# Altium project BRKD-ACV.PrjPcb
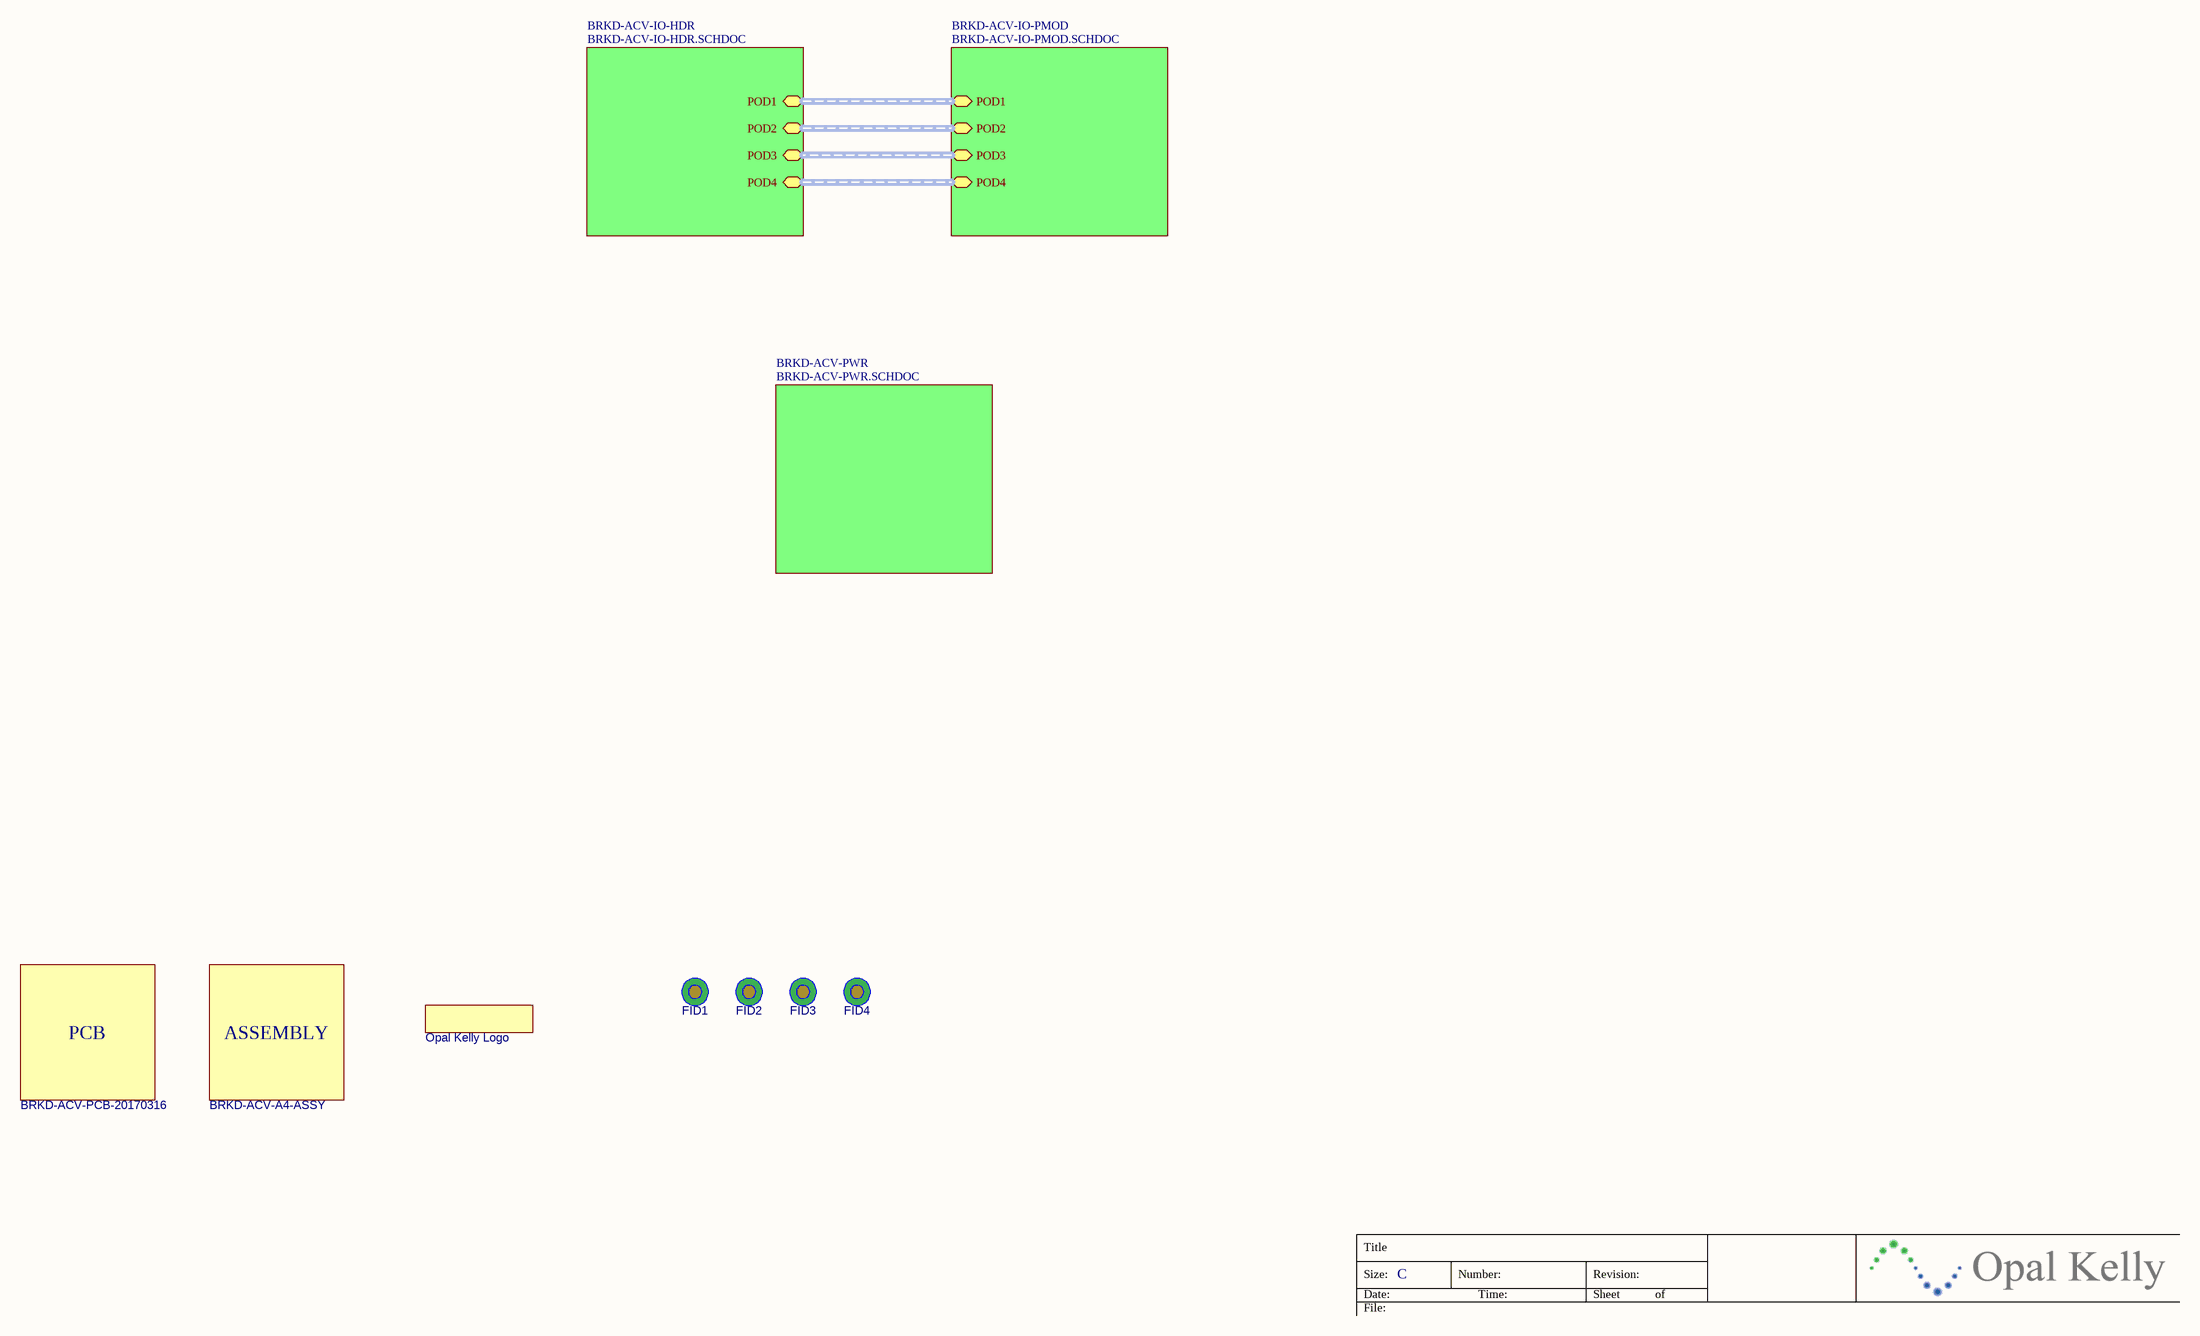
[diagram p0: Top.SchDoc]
Assembly_Part_Num: BRKD-ACV; Assembly_Revision: C01; PCB_Part_Num: BRKD-ACV-PCB; PCB_Revision: 20170316
4 sheets, 173 parts. Net scope: hierarchical (ports join the sheet entries above them; power ports are global).
Board file: BRKD-ACV.PcbDoc
Sheets:
  Top.SchDoc
    BRKD-ACV-IO-HDR = BRKD-ACV-IO-HDR.SCHDOC
    BRKD-ACV-IO-PMOD = BRKD-ACV-IO-PMOD.SCHDOC
    BRKD-ACV-PWR = BRKD-ACV-PWR.SCHDOC

## Sheet Top.SchDoc: FOMD-ACV Breakout Board - Top
size C; Organization: Opal Kelly; Address1: 13500 SW 72nd Ave; Address2: Suite 120; Address3: Portland, OR  97223; Address4: http://www.opalkelly.com; DocumentNumber: xxx; Revision: 1; SheetNumber: 1; SheetTotal: 4; PageSetup: Record=PageOptions¦CenterHorizontal=True¦CenterVertical=True¦PrintScale=0.52¦XCorrection=1.00¦YCorrection=1.00¦PrintKind=0¦BorderSize=5000000¦LeftOffset=0¦BottomOffset=0¦Orientation=2¦PaperLength=1000¦PaperWidth=1000¦Scale=100¦PaperSource=15¦PrintQuality=600¦MediaType=1¦DitherType=10¦PaperKind=Letter¦PrintScaleMode=1

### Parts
*1  Opal Kelly Logo  [okLogo-23x5]
ASSY1  BRKD-ACV-A4-ASSY  (mechanical)
FID1  FIDUCIAL  [FID1MM/2MM-SS]  (value not drawn)
FID2  FIDUCIAL  [FID1MM/2MM-SS]  (value not drawn)
FID3  FIDUCIAL  [FID1MM/2MM-SS]  (value not drawn)
FID4  FIDUCIAL  [FID1MM/2MM-SS]  (value not drawn)
PCB?  BRKD-ACV-PCB-20170316  (mechanical)

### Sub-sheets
BRKD-ACV-IO-HDR = BRKD-ACV-IO-HDR.SCHDOC: POD1 (harness POD), POD2 (harness POD), POD3 (harness POD), POD4 (harness POD)
BRKD-ACV-IO-PMOD = BRKD-ACV-IO-PMOD.SCHDOC: POD1 (harness POD), POD2 (harness POD), POD3 (harness POD), POD4 (harness POD)
BRKD-ACV-PWR = BRKD-ACV-PWR.SCHDOC: no entries

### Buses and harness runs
harness sheet BRKD-ACV-IO-HDR/POD1 = sheet BRKD-ACV-IO-PMOD/POD1
harness sheet BRKD-ACV-IO-HDR/POD2 = sheet BRKD-ACV-IO-PMOD/POD2
harness sheet BRKD-ACV-IO-HDR/POD3 = sheet BRKD-ACV-IO-PMOD/POD3
harness sheet BRKD-ACV-IO-HDR/POD4 = sheet BRKD-ACV-IO-PMOD/POD4

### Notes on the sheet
- Title
- Size:
- Date:
- File:
- C
- Number:
- Time:
- Revision:
- Sheet
- of

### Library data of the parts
*1 = OKLOGO
ASSY1 = 001379: BRKD-ACV-A4 PCB assembly; Manufacturer: PCB Assembly Cost; partnumber: 001379
FID1-FID4 = FIDUCIAL: PCB fiducial
PCB? = 001516: PCB for BRKD-ACV; Manufacturer: Generic PCB Manufacturer; partnumber: 001516; x_lifecycle_status: Prototype

## Sheet BRKD-ACV-IO-HDR.SCHDOC: FOMD-ACV Breakout Board - Headers
size C; Organization: Opal Kelly; Address1: 13500 SW 72nd Ave; Address2: STE 100; Address3: (217)391-3724; Address4: http://www.opalkelly.com; DocumentNumber: 1; Revision: 1.0; SheetNumber: 1; SheetTotal: 3
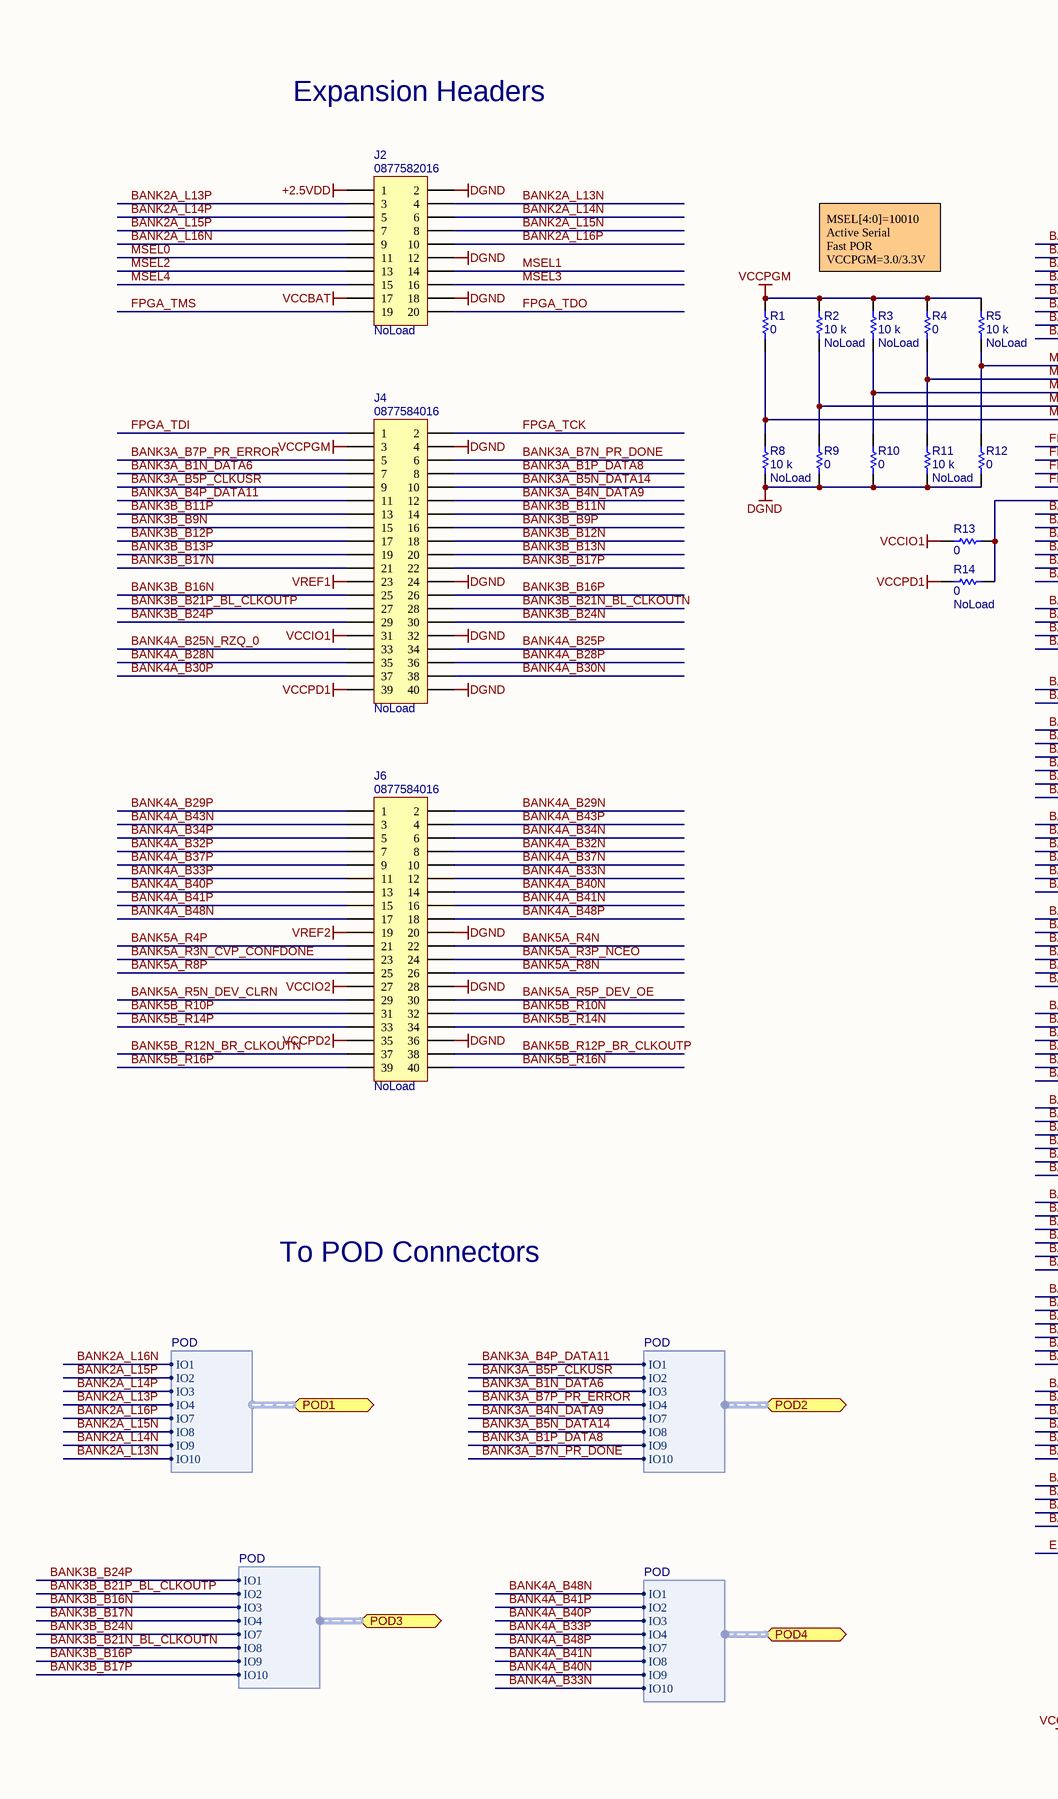
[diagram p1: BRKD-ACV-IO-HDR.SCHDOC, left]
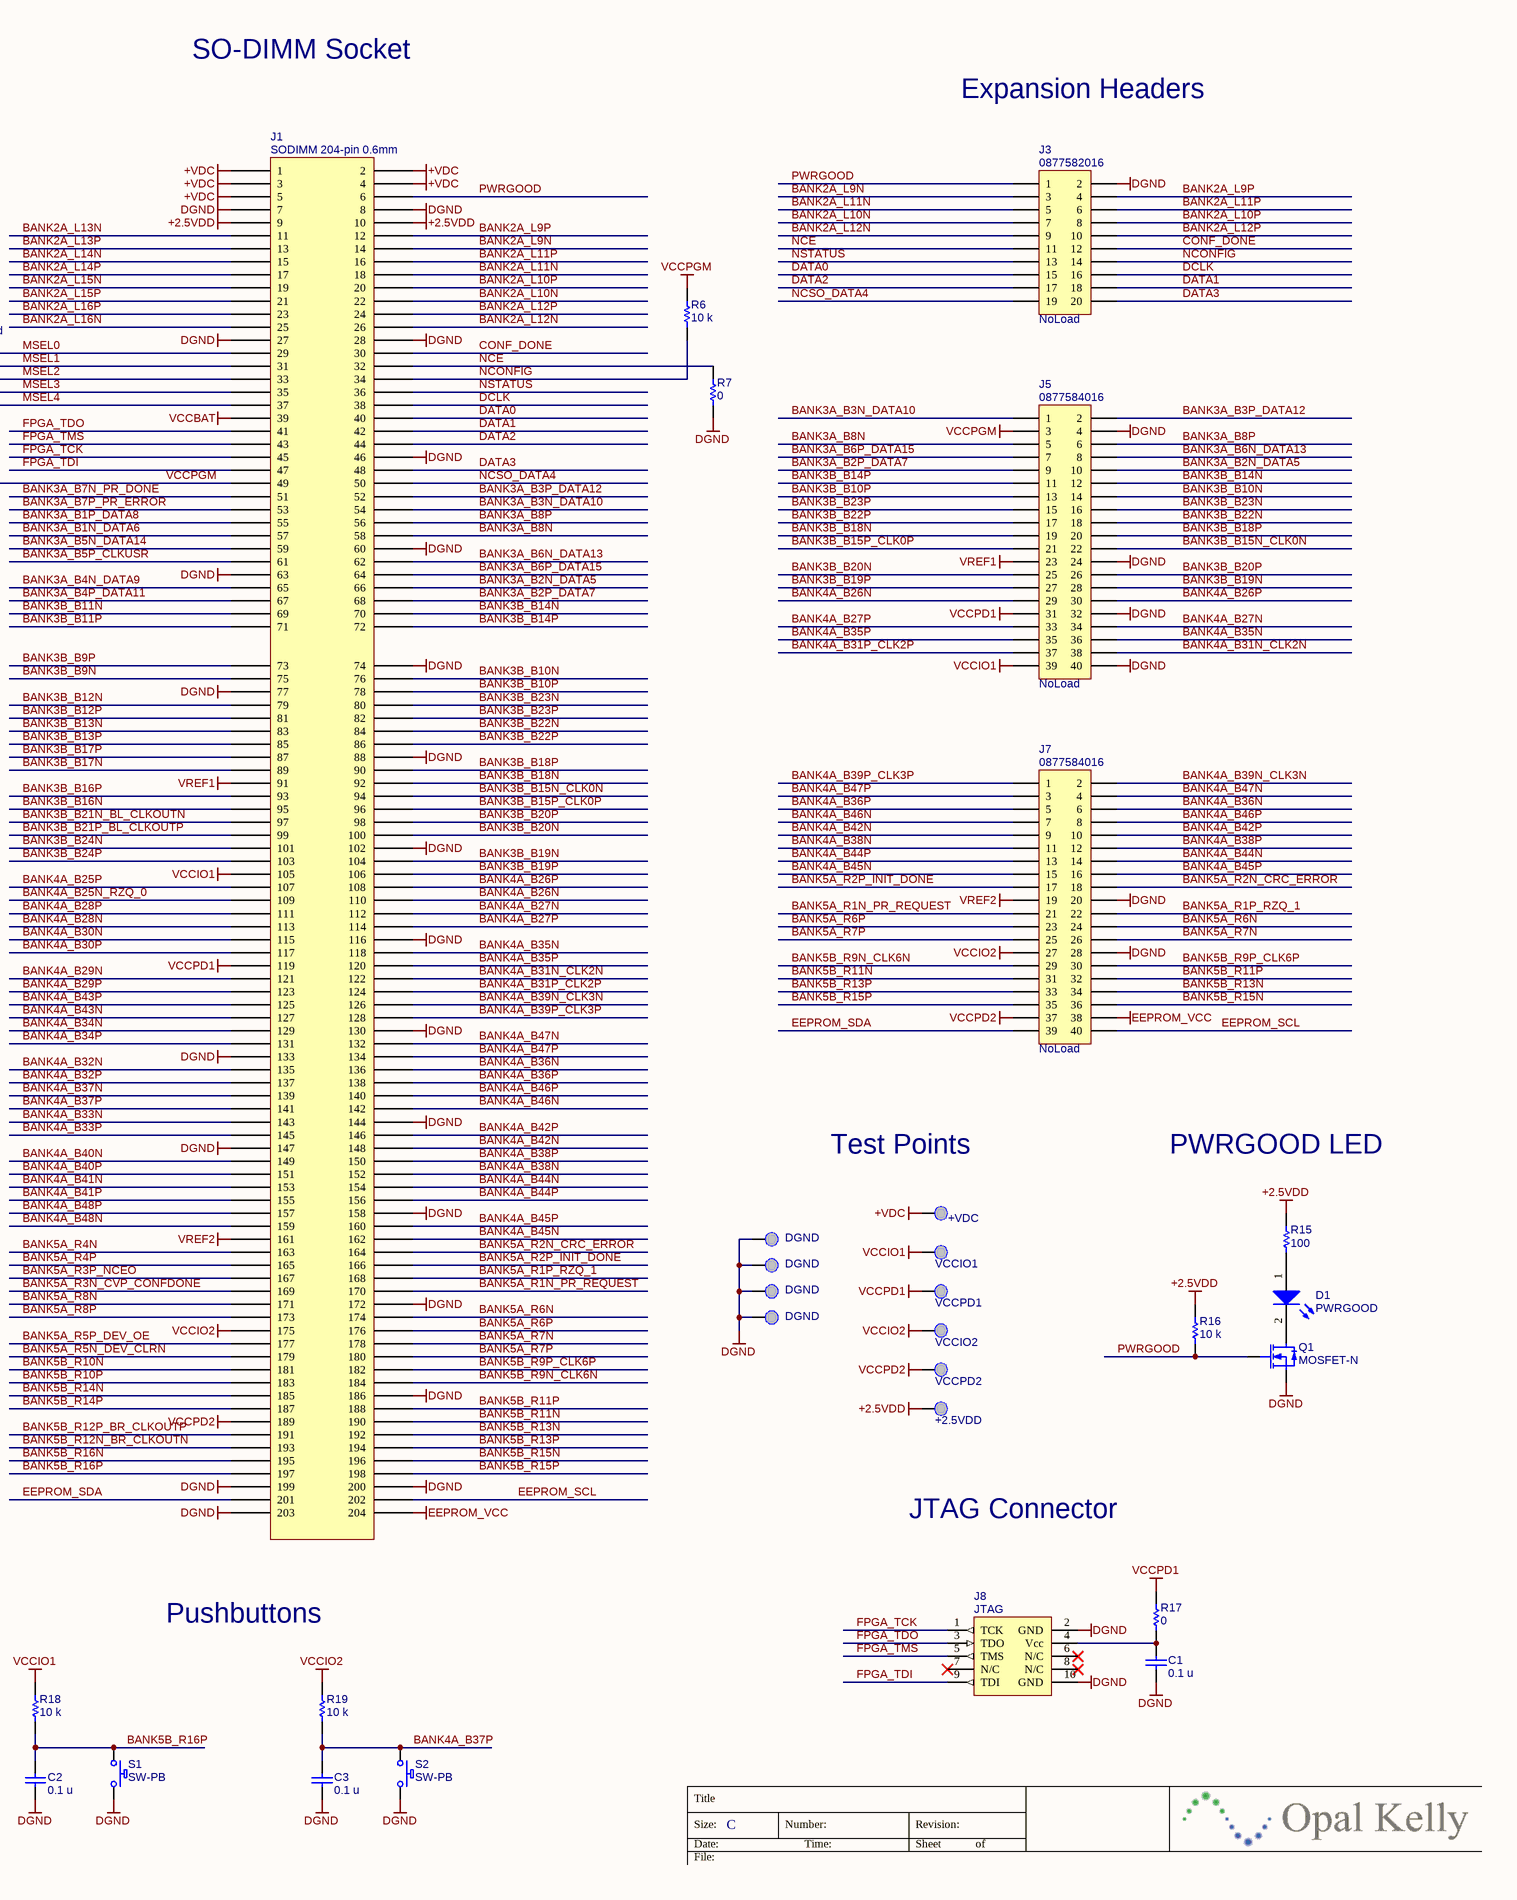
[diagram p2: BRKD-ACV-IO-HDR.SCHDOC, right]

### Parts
C1  value 0.1 u  [CAPC1005X06N]  (hidden comment: C0402C104K8PACTU)
C2  value 0.1 u  [CAPC1005X06N]  (hidden comment: C0402C104K8PACTU)
C3  value 0.1 u  [CAPC1005X06N]  (hidden comment: C0402C104K8PACTU)
D1  PWRGOOD  [CD1608-0603]
J1  SODIMM 204-pin 0.6mm  [2013289]
J2  0877582016  [HDR2X10-2MM]
J3  0877582016  [HDR2X10-2MM]
J4  0877584016  [HDR2X20-2MM]
J5  0877584016  [HDR2X20-2MM]
J6  0877584016  [HDR2X20-2MM]
J7  0877584016  [HDR2X20-2MM]
J8  JTAG  [HDR2X5-SHRD]
Q1  MOSFET-N  [SOT23-95P240X110]
R1  value 0  [RESC1005X06N]  (hidden comment: CRCW04020000Z0ED)
R2  value 10 k  [RESC1005X06N]  (hidden comment: CRCW040210K0JNED)
R3  value 10 k  [RESC1005X06N]  (hidden comment: CRCW040210K0JNED)
R4  value 0  [RESC1005X06N]  (hidden comment: CRCW04020000Z0ED)
R5  value 10 k  [RESC1005X06N]  (hidden comment: CRCW040210K0JNED)
R6  value 10 k  [RESC1005X06N]  (hidden comment: CRCW040210K0JNED)
R7  value 0  [RESC1005X06N]  (hidden comment: CRCW04020000Z0ED)
R8  value 10 k  [RESC1005X06N]  (hidden comment: CRCW040210K0JNED)
R9  value 0  [RESC1005X06N]  (hidden comment: CRCW04020000Z0ED)
R10  value 0  [RESC1005X06N]  (hidden comment: CRCW04020000Z0ED)
R11  value 10 k  [RESC1005X06N]  (hidden comment: CRCW040210K0JNED)
R12  value 0  [RESC1005X06N]  (hidden comment: CRCW04020000Z0ED)
R13  value 0  [RESC1608N]  (hidden comment: CRCW06030000Z0EA)
R14  value 0  [RESC1608N]  (hidden comment: CRCW06030000Z0EA)
R15  value 100  [RESC1005X06N]  (hidden comment: CRCW0402100RFKED)
R16  value 10 k  [RESC1005X06N]  (hidden comment: CRCW040210K0JNED)
R17  value 0  [RESC1608N]  (hidden comment: CRCW06030000Z0EA)
R18  value 10 k  [RESC1005X06N]  (hidden comment: CRCW040210K0JNED)
R19  value 10 k  [RESC1005X06N]  (hidden comment: CRCW040210K0JNED)
S1  SW-PB  [SW_BFS]
S2  SW-PB  [SW_BFS]
TP1  +VDC  [TP_MED]
TP2  DGND  [TP_MED]
TP3  VCCIO1  [TP_MED]
TP4  DGND  [TP_MED]
TP5  DGND  [TP_MED]
TP6  VCCPD1  [TP_MED]
TP7  DGND  [TP_MED]
TP8  VCCIO2  [TP_MED]
TP9  VCCPD2  [TP_MED]
TP10  +2.5VDD  [TP_MED]

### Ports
POD1 (harness POD), POD2 (harness POD), POD3 (harness POD), POD4 (harness POD)

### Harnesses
POD: IO1, IO2, IO3, IO4, IO7, IO8, IO9, IO10

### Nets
+2.5VDD: J1.9 J1.10 J2.1 R15.2 R16.2 TP10.1(PIN)
+VDC: J1.1 J1.2 J1.3 J1.4 J1.5 TP1.1(PIN)
DGND: C1.1 C2.1 C3.1 J1.7 J1.8 J1.27 J1.28 J1.46 J1.60 J1.63 J1.74 J1.77 J1.88 J1.102 J1.116 J1.130 J1.133 J1.144 J1.147 J1.158 J1.172 J1.186 J1.199 J1.200 J1.203 J2.2 J2.12 J2.18 J3.2 J4.4 J4.24 J4.32 J4.40 J5.4 J5.24 J5.32 J5.40 J6.20 J6.28 J6.36 J7.20 J7.28 J8.2(GND) J8.10(GND) Q1.2(S) R7.1 R8.2 R9.1 R10.1 R11.2 R12.1 S1.2 S2.2 TP2.1(PIN) TP4.1(PIN) TP5.1(PIN) TP7.1(PIN)
EEPROM_VCC: J1.204 J7.38
VCCBAT: J1.39 J2.17
VCCIO1: J1.105 J4.31 J5.39 R13.1 R18.2 TP3.1(PIN)
VCCIO2: J1.175 J6.27 J7.27 R19.2 TP8.1(PIN)
VCCPD1: J1.119 J4.39 J5.31 R14.1 R17.2 TP6.1(PIN)
VCCPD2: J1.189 J6.35 J7.37 TP9.1(PIN)
VCCPGM: J1.49 J4.3 J5.3 R1.2 R2.2 R3.1 R4.2 R5.1 R6.2 R13.2 R14.2
VREF1: J1.91 J4.23 J5.23
VREF2: J1.161 J6.19 J7.19
BANK2A_L9N: J1.14 J3.3
BANK2A_L9P: J1.12 J3.4
BANK2A_L10N: J1.22 J3.7
BANK2A_L10P: J1.20 J3.8
BANK2A_L11N: J1.18 J3.5
BANK2A_L11P: J1.16 J3.6
BANK2A_L12N: J1.26 J3.9
BANK2A_L12P: J1.24 J3.10
BANK2A_L13N: J1.11 J2.4 ; port POD1.IO10
BANK2A_L13P: J1.13 J2.3 ; port POD1.IO4
BANK2A_L14N: J1.15 J2.6 ; port POD1.IO9
BANK2A_L14P: J1.17 J2.5 ; port POD1.IO3
BANK2A_L15N: J1.19 J2.8 ; port POD1.IO8
BANK2A_L15P: J1.21 J2.7 ; port POD1.IO2
BANK2A_L16N: J1.25 J2.9 ; port POD1.IO1
BANK2A_L16P: J1.23 J2.10 ; port POD1.IO7
BANK3A_B1N_DATA6: J1.57 J4.7 ; port POD2.IO3
BANK3A_B1P_DATA8: J1.55 J4.8 ; port POD2.IO9
BANK3A_B2N_DATA5: J1.66 J5.10
BANK3A_B2P_DATA7: J1.68 J5.9
BANK3A_B3N_DATA10: J1.54 J5.1
BANK3A_B3P_DATA12: J1.52 J5.2
BANK3A_B4N_DATA9: J1.65 J4.12 ; port POD2.IO7
BANK3A_B4P_DATA11: J1.67 J4.11 ; port POD2.IO1
BANK3A_B5N_DATA14: J1.59 J4.10 ; port POD2.IO8
BANK3A_B5P_CLKUSR: J1.61 J4.9 ; port POD2.IO2
BANK3A_B6N_DATA13: J1.62 J5.8
BANK3A_B6P_DATA15: J1.64 J5.7
BANK3A_B7N_PR_DONE: J1.51 J4.6 ; port POD2.IO10
BANK3A_B7P_PR_ERROR: J1.53 J4.5 ; port POD2.IO4
BANK3A_B8N: J1.58 J5.5
BANK3A_B8P: J1.56 J5.6
BANK3B_B9N: J1.75 J4.15
BANK3B_B9P: J1.73 J4.16
BANK3B_B10N: J1.76 J5.14
BANK3B_B10P: J1.78 J5.13
BANK3B_B11N: J1.69 J4.14
BANK3B_B11P: J1.71 J4.13
BANK3B_B12N: J1.79 J4.18
BANK3B_B12P: J1.81 J4.17
BANK3B_B13N: J1.83 J4.20
BANK3B_B13P: J1.85 J4.19
BANK3B_B14N: J1.70 J5.12
BANK3B_B14P: J1.72 J5.11
BANK3B_B15N_CLK0N: J1.94 J5.22
BANK3B_B15P_CLK0P: J1.96 J5.21
BANK3B_B16N: J1.95 J4.25 ; port POD3.IO3
BANK3B_B16P: J1.93 J4.26 ; port POD3.IO9
BANK3B_B17N: J1.89 J4.21 ; port POD3.IO4
BANK3B_B17P: J1.87 J4.22 ; port POD3.IO10
BANK3B_B18N: J1.92 J5.19
BANK3B_B18P: J1.90 J5.20
BANK3B_B19N: J1.104 J5.28
BANK3B_B19P: J1.106 J5.27
BANK3B_B20N: J1.100 J5.25
BANK3B_B20P: J1.98 J5.26
BANK3B_B21N_BL_CLKOUTN: J1.97 J4.28 ; port POD3.IO8
BANK3B_B21P_BL_CLKOUTP: J1.99 J4.27 ; port POD3.IO2
BANK3B_B22N: J1.84 J5.18
BANK3B_B22P: J1.86 J5.17
BANK3B_B23N: J1.80 J5.16
BANK3B_B23P: J1.82 J5.15
BANK3B_B24N: J1.101 J4.30 ; port POD3.IO7
BANK3B_B24P: J1.103 J4.29 ; port POD3.IO1
BANK4A_B25N_RZQ_0: J1.109 J4.33
BANK4A_B25P: J1.107 J4.34
BANK4A_B26N: J1.110 J5.29
BANK4A_B26P: J1.108 J5.30
BANK4A_B27N: J1.112 J5.34
BANK4A_B27P: J1.114 J5.33
BANK4A_B28N: J1.113 J4.35
BANK4A_B28P: J1.111 J4.36
BANK4A_B29N: J1.121 J6.2
BANK4A_B29P: J1.123 J6.1
BANK4A_B30N: J1.115 J4.38
BANK4A_B30P: J1.117 J4.37
BANK4A_B31N_CLK2N: J1.122 J5.38
BANK4A_B31P_CLK2P: J1.124 J5.37
BANK4A_B32N: J1.135 J6.8
BANK4A_B32P: J1.137 J6.7
BANK4A_B33N: J1.143 J6.12 ; port POD4.IO10
BANK4A_B33P: J1.145 J6.11 ; port POD4.IO4
BANK4A_B34N: J1.129 J6.6
BANK4A_B34P: J1.131 J6.5
BANK4A_B35N: J1.118 J5.36
BANK4A_B35P: J1.120 J5.35
BANK4A_B36N: J1.136 J7.6
BANK4A_B36P: J1.138 J7.5
BANK4A_B37N: J1.139 J6.10
BANK4A_B37P: C3.2 J1.141 J6.9 R19.1 S2.1
BANK4A_B38N: J1.152 J7.11
BANK4A_B38P: J1.150 J7.12
BANK4A_B39N_CLK3N: J1.126 J7.2
BANK4A_B39P_CLK3P: J1.128 J7.1
BANK4A_B40N: J1.149 J6.14 ; port POD4.IO9
BANK4A_B40P: J1.151 J6.13 ; port POD4.IO3
BANK4A_B41N: J1.153 J6.16 ; port POD4.IO8
BANK4A_B41P: J1.155 J6.15 ; port POD4.IO2
BANK4A_B42N: J1.148 J7.9
BANK4A_B42P: J1.146 J7.10
BANK4A_B43N: J1.127 J6.3
BANK4A_B43P: J1.125 J6.4
BANK4A_B44N: J1.154 J7.14
BANK4A_B44P: J1.156 J7.13
BANK4A_B45N: J1.162 J7.15
BANK4A_B45P: J1.160 J7.16
BANK4A_B46N: J1.142 J7.7
BANK4A_B46P: J1.140 J7.8
BANK4A_B47N: J1.132 J7.4
BANK4A_B47P: J1.134 J7.3
BANK4A_B48N: J1.159 J6.17 ; port POD4.IO1
BANK4A_B48P: J1.157 J6.18 ; port POD4.IO7
BANK5A_R1N_PR_REQUEST: J1.170 J7.21
BANK5A_R1P_RZQ_1: J1.168 J7.22
BANK5A_R2N_CRC_ERROR: J1.164 J7.18
BANK5A_R2P_INIT_DONE: J1.166 J7.17
BANK5A_R3N_CVP_CONFDONE: J1.169 J6.23
BANK5A_R3P_NCEO: J1.167 J6.24
BANK5A_R4N: J1.163 J6.22
BANK5A_R4P: J1.165 J6.21
BANK5A_R5N_DEV_CLRN: J1.179 J6.29
BANK5A_R5P_DEV_OE: J1.177 J6.30
BANK5A_R6N: J1.174 J7.24
BANK5A_R6P: J1.176 J7.23
BANK5A_R7N: J1.178 J7.26
BANK5A_R7P: J1.180 J7.25
BANK5A_R8N: J1.171 J6.26
BANK5A_R8P: J1.173 J6.25
BANK5B_R9N_CLK6N: J1.184 J7.29
BANK5B_R9P_CLK6P: J1.182 J7.30
BANK5B_R10N: J1.181 J6.32
BANK5B_R10P: J1.183 J6.31
BANK5B_R11N: J1.190 J7.31
BANK5B_R11P: J1.188 J7.32
BANK5B_R12N_BR_CLKOUTN: J1.193 J6.37
BANK5B_R12P_BR_CLKOUTP: J1.191 J6.38
BANK5B_R13N: J1.192 J7.34
BANK5B_R13P: J1.194 J7.33
BANK5B_R14N: J1.185 J6.34
BANK5B_R14P: J1.187 J6.33
BANK5B_R15N: J1.196 J7.36
BANK5B_R15P: J1.198 J7.35
BANK5B_R16N: J1.195 J6.40
BANK5B_R16P: C2.2 J1.197 J6.39 R18.1 S1.1
CONF_DONE: J1.30 J3.12
DATA0: J1.40 J3.15
DATA1: J1.42 J3.18
DATA2: J1.44 J3.17
DATA3: J1.48 J3.20
DCLK: J1.38 J3.16
EEPROM_SCL: J1.202 J7.40
EEPROM_SDA: J1.201 J7.39
FPGA_TCK: J1.45 J4.2 J8.1(TCK)
FPGA_TDI: J1.47 J4.1 J8.9(TDI)
FPGA_TDO: J1.41 J2.20 J8.3(TDO)
FPGA_TMS: J1.43 J2.19 J8.5(TMS)
MSEL0: J1.29 J2.11 R5.2 R12.2
MSEL1: J1.31 J2.14 R4.1 R11.1
MSEL2: J1.33 J2.13 R3.2 R10.2
MSEL3: J1.35 J2.16 R2.1 R9.2
MSEL4: J1.37 J2.15 R1.1 R8.1
NCE: J1.32 J3.11 R7.2
NCONFIG: J1.34 J3.14 R6.1
NCSO_DATA4: J1.50 J3.19
NSTATUS: J1.36 J3.13
PWRGOOD: J1.6 J3.1 Q1.1(G) R16.1
NetC1_2: C1.2 J8.4(Vcc) R17.1
NetD1_1: D1.1(A) R15.1
NetD1_2: D1.2(K) Q1.3(D)

Not connected (* = marked no-connect by the designer): J8 6(N/C)* 7(N/C)* 8(N/C)*

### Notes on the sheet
- Expansion Headers
- SO-DIMM Socket
- MSEL[4:0]=10010
  Active Serial
  Fast POR
  VCCPGM=3.0/3.3V
- Test Points
- PWRGOOD LED
- To POD Connectors
- JTAG Connector
- Pushbuttons
- Title
- Size:
- Date:
- File:
- C
- Number:
- Time:
- Revision:
- Sheet
- of

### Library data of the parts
C1-C3 = 000070: Ceramic capacitor; Manufacturer: Kemet; partnumber: 000070; Description 2: SM-0402, 10%, 10v; ValueFloat: 1E-7; Tolerance (%): 10
D1 = 000012: LED; Manufacturer: Lite-On; Manufacturer_PN: LTST-C190GKT; partnumber: 000012; Description 2: SM-0603, green
J1 = 001370: SODIMM socket, DDR3, 204-pin, gold flash, 5.2mm height, surface-mount; Manufacturer: AMP / Tyco; Manufacturer_PN: 2-2013289-1; partnumber: 001370
J2 J3 = 001338: 2mm header, 10x2, thru-hole; Manufacturer: Molex; partnumber: 001338; Description 2: 15µin gold finish, vertical mount; x_lifecycle_status: Production
J4-J7 = 000583: 2mm header, 20x2, thru-hole; Manufacturer: Molex; partnumber: 000583
J8 = 000777: 2.54mm, 10 Pos, Dual Row Header; Manufacturer: Molex; Manufacturer_PN: 70246-1004; partnumber: 000777; Description 2: Altera JTAG Compatible
Q1 = 001237: N-Channel, Logic Level, MOSFET; PartNumber: 001237; Manufacturer: Fairchild Semiconductor; Manufacturer_PN: FDN337N; PackageDocument: 1995/1996; Description 2: 2.2A, 30V
R1 R4 R7 R9 R10 R12 = 000755: Thick-film resistor; Manufacturer: Vishay; partnumber: 000755; Description 2: SM-0402, 1%, 1/16W; Tolerance (%): 1
R2 R3 R5 R6 R8 R11 R16 R18 R19 = 000759: Thick-film resistor; Manufacturer: Vishay; partnumber: 000759; Description 2: SM-0402, 5%, 1/16W; ValueFloat: 10000; Tolerance (%): 5
R13 R14 R17 = 000411: Zero-ohm resistor; Manufacturer: Vishay; partnumber: 000411; Description 2: SM-0603, 1/10W, 20 mOhm max
R15 = 000827: Thick-film resistor; Manufacturer: Vishay; partnumber: 000827; Description 2: SM-0402, 1%, 1/16W; Tolerance (%): 1
S1 S2 = 000010: Pushbutton; Manufacturer: Omron; PartNumber: 000010; Manufacturer_PN: B3FS-1000P; Description 2: SMD, tactile; x_lifecycle_status: Production
TP1-TP10 = 000265: Testpoint; Manufacturer: Keystone Electronics; Manufacturer_PN: 5007; partnumber: 000265; Description 2: 0.063 in. diameter, compact, White

## Sheet BRKD-ACV-IO-PMOD.SCHDOC: FOMD-ACV Breakout Board - PMOD
size C; Organization: Opal Kelly; Address1: 13500 SW 72nd Ave; Address2: STE 100; Address3: (217)391-3724; Address4: http://www.opalkelly.com; DocumentNumber: 1; Revision: 1.0; SheetNumber: 2; SheetTotal: 3
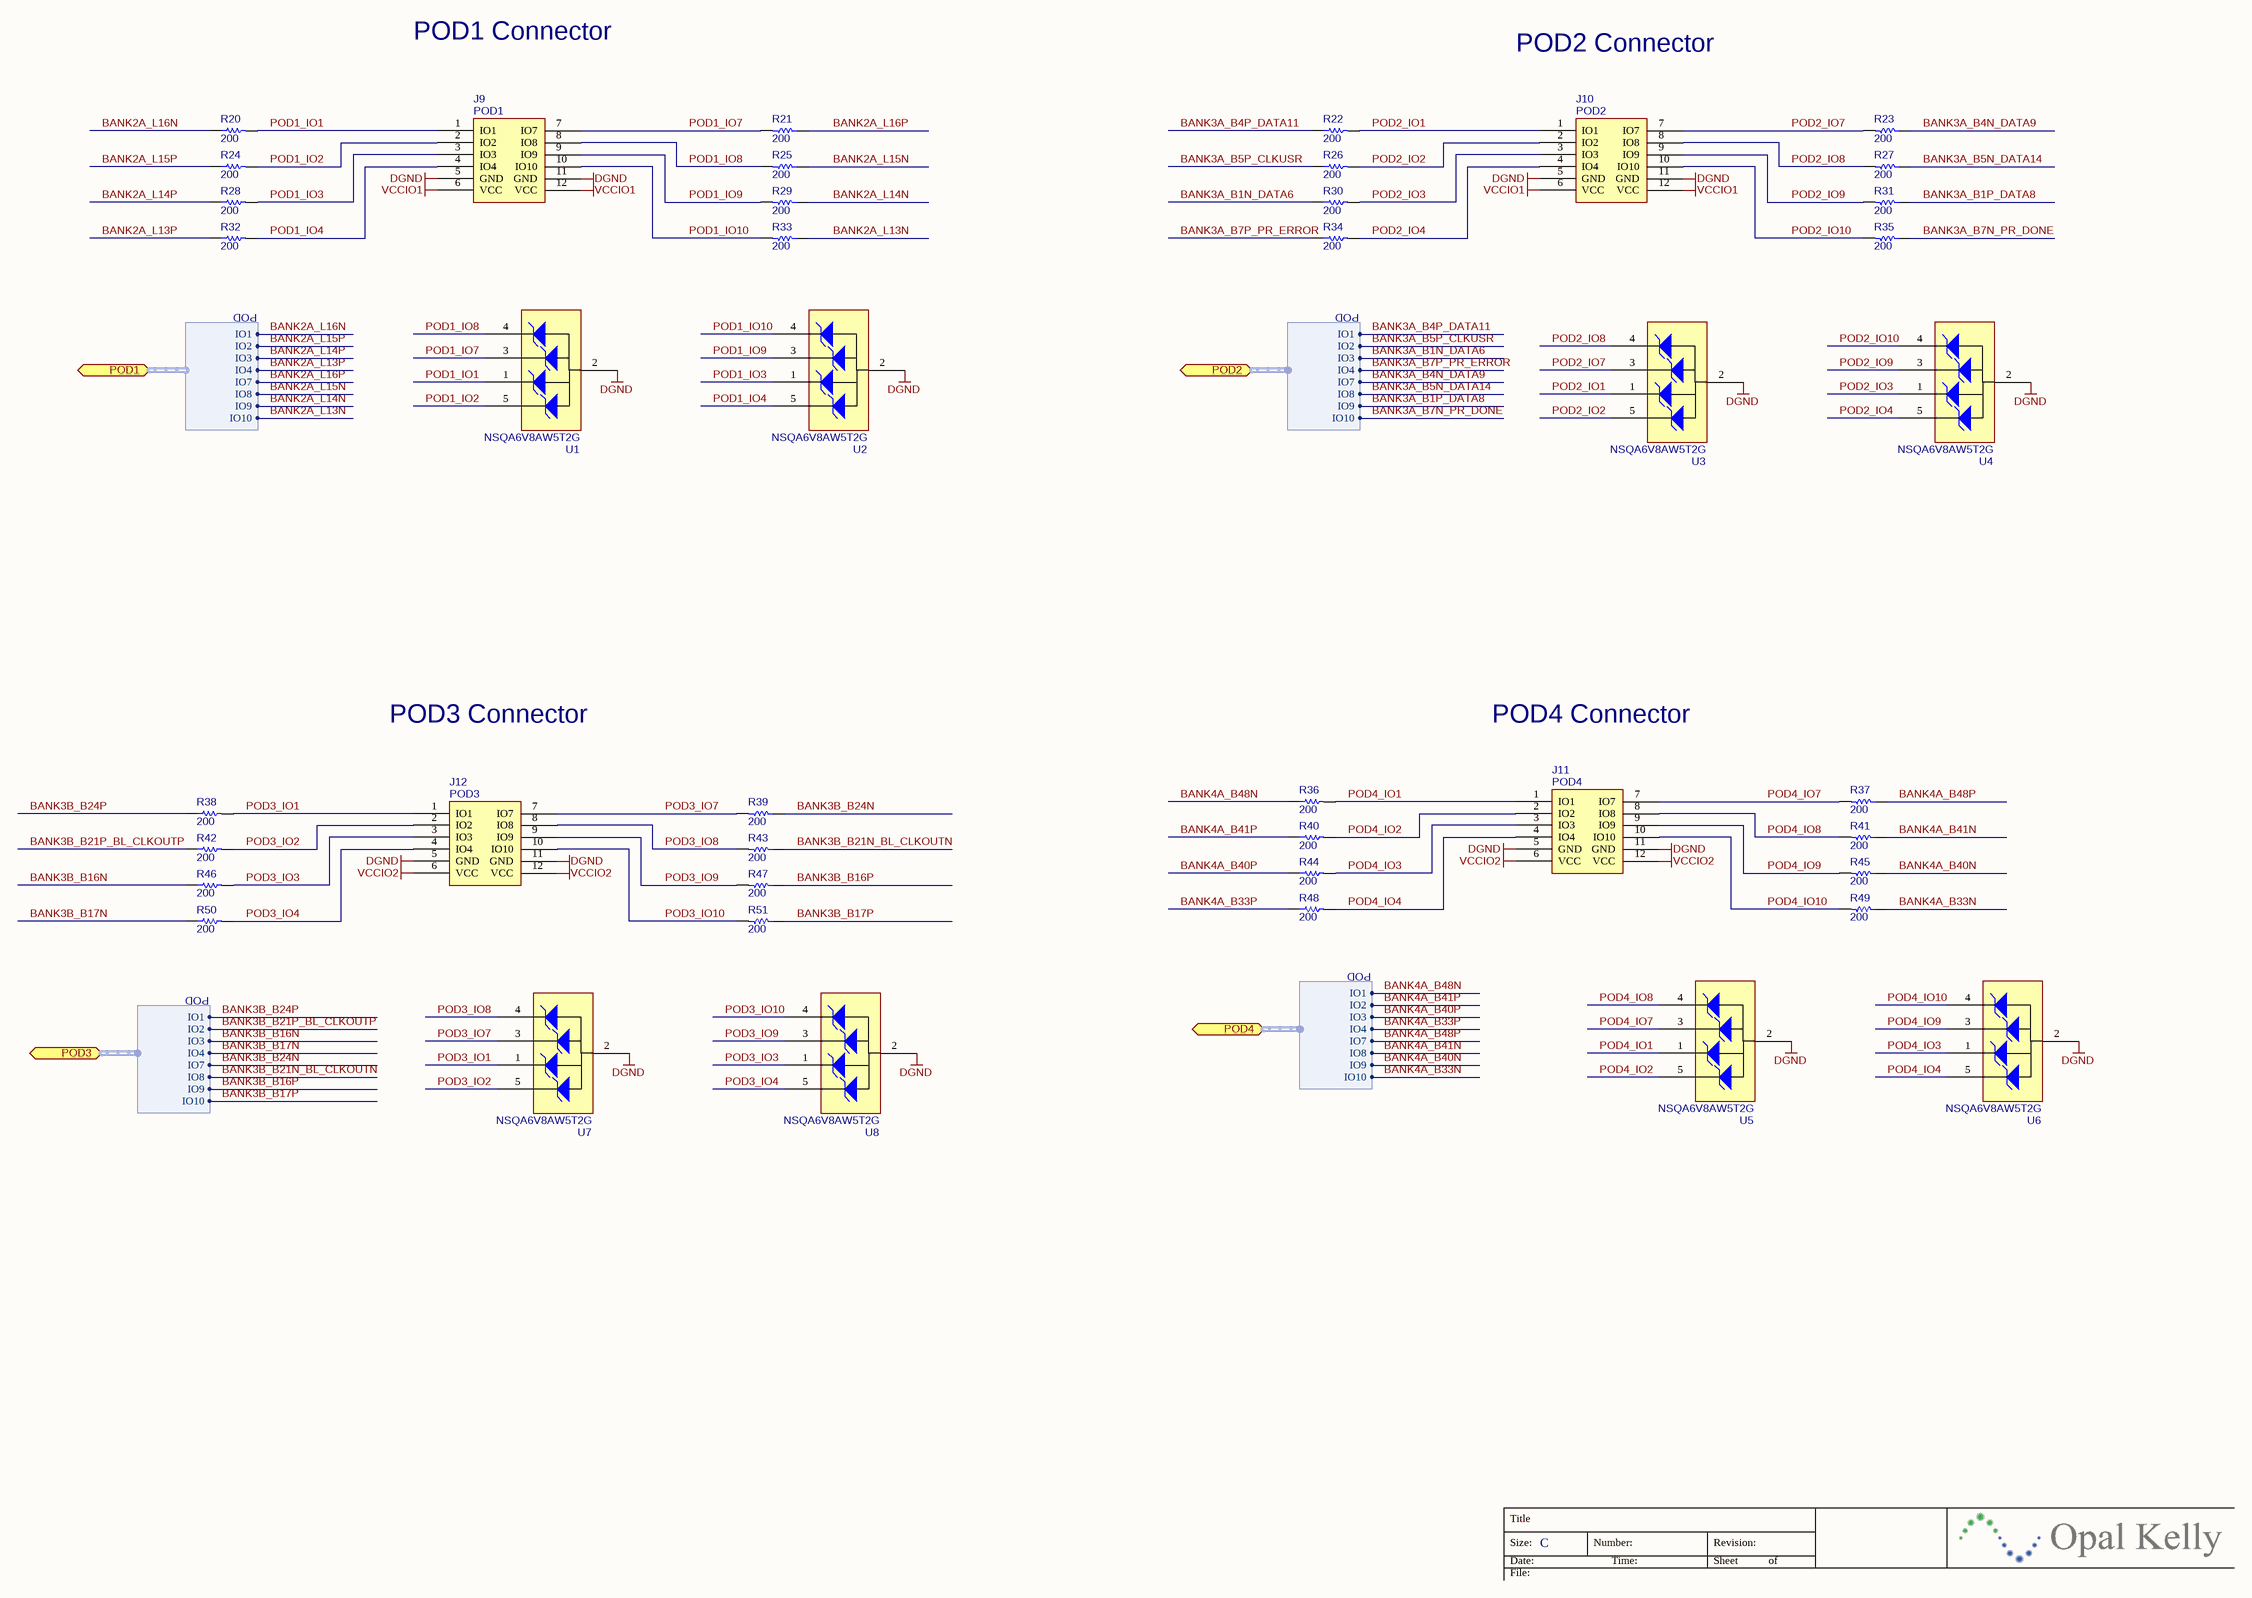
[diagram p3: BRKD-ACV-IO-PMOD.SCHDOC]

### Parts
J9  POD1  [HDR2X6_CEN_RA]
J10  POD2  [HDR2X6_CEN_RA]
J11  POD4  [HDR2X6_CEN_RA]
J12  POD3  [HDR2X6_CEN_RA]
R20  value 200  [RESC1005X06N]  (hidden comment: CRCW0402200RFKED)
R21  value 200  [RESC1005X06N]  (hidden comment: CRCW0402200RFKED)
R22  value 200  [RESC1005X06N]  (hidden comment: CRCW0402200RFKED)
R23  value 200  [RESC1005X06N]  (hidden comment: CRCW0402200RFKED)
R24  value 200  [RESC1005X06N]  (hidden comment: CRCW0402200RFKED)
R25  value 200  [RESC1005X06N]  (hidden comment: CRCW0402200RFKED)
R26  value 200  [RESC1005X06N]  (hidden comment: CRCW0402200RFKED)
R27  value 200  [RESC1005X06N]  (hidden comment: CRCW0402200RFKED)
R28  value 200  [RESC1005X06N]  (hidden comment: CRCW0402200RFKED)
R29  value 200  [RESC1005X06N]  (hidden comment: CRCW0402200RFKED)
R30  value 200  [RESC1005X06N]  (hidden comment: CRCW0402200RFKED)
R31  value 200  [RESC1005X06N]  (hidden comment: CRCW0402200RFKED)
R32  value 200  [RESC1005X06N]  (hidden comment: CRCW0402200RFKED)
R33  value 200  [RESC1005X06N]  (hidden comment: CRCW0402200RFKED)
R34  value 200  [RESC1005X06N]  (hidden comment: CRCW0402200RFKED)
R35  value 200  [RESC1005X06N]  (hidden comment: CRCW0402200RFKED)
R36  value 200  [RESC1005X06N]  (hidden comment: CRCW0402200RFKED)
R37  value 200  [RESC1005X06N]  (hidden comment: CRCW0402200RFKED)
R38  value 200  [RESC1005X06N]  (hidden comment: CRCW0402200RFKED)
R39  value 200  [RESC1005X06N]  (hidden comment: CRCW0402200RFKED)
R40  value 200  [RESC1005X06N]  (hidden comment: CRCW0402200RFKED)
R41  value 200  [RESC1005X06N]  (hidden comment: CRCW0402200RFKED)
R42  value 200  [RESC1005X06N]  (hidden comment: CRCW0402200RFKED)
R43  value 200  [RESC1005X06N]  (hidden comment: CRCW0402200RFKED)
R44  value 200  [RESC1005X06N]  (hidden comment: CRCW0402200RFKED)
R45  value 200  [RESC1005X06N]  (hidden comment: CRCW0402200RFKED)
R46  value 200  [RESC1005X06N]  (hidden comment: CRCW0402200RFKED)
R47  value 200  [RESC1005X06N]  (hidden comment: CRCW0402200RFKED)
R48  value 200  [RESC1005X06N]  (hidden comment: CRCW0402200RFKED)
R49  value 200  [RESC1005X06N]  (hidden comment: CRCW0402200RFKED)
R50  value 200  [RESC1005X06N]  (hidden comment: CRCW0402200RFKED)
R51  value 200  [RESC1005X06N]  (hidden comment: CRCW0402200RFKED)
U1  NSQA6V8AW5T2G  [SOT-323-5]
U2  NSQA6V8AW5T2G  [SOT-323-5]
U3  NSQA6V8AW5T2G  [SOT-323-5]
U4  NSQA6V8AW5T2G  [SOT-323-5]
U5  NSQA6V8AW5T2G  [SOT-323-5]
U6  NSQA6V8AW5T2G  [SOT-323-5]
U7  NSQA6V8AW5T2G  [SOT-323-5]
U8  NSQA6V8AW5T2G  [SOT-323-5]

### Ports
POD1 (harness POD), POD2 (harness POD), POD3 (harness POD), POD4 (harness POD)

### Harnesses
POD: IO1, IO2, IO3, IO4, IO7, IO8, IO9, IO10

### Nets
DGND: J9.5(GND) J9.11(GND) J10.5(GND) J10.11(GND) J11.5(GND) J11.11(GND) J12.5(GND) J12.11(GND) U1.2 U2.2 U3.2 U4.2 U5.2 U6.2 U7.2 U8.2
VCCIO1: J9.6(VCC) J9.12(VCC) J10.6(VCC) J10.12(VCC)
VCCIO2: J11.6(VCC) J11.12(VCC) J12.6(VCC) J12.12(VCC)
BANK2A_L13N: R33.1 ; port POD1.IO10
BANK2A_L13P: R32.1 ; port POD1.IO4
BANK2A_L14N: R29.1 ; port POD1.IO9
BANK2A_L14P: R28.1 ; port POD1.IO3
BANK2A_L15N: R25.1 ; port POD1.IO8
BANK2A_L15P: R24.1 ; port POD1.IO2
BANK2A_L16N: R20.1 ; port POD1.IO1
BANK2A_L16P: R21.1 ; port POD1.IO7
BANK3A_B1N_DATA6: R30.1 ; port POD2.IO3
BANK3A_B1P_DATA8: R31.1 ; port POD2.IO9
BANK3A_B4N_DATA9: R23.1 ; port POD2.IO7
BANK3A_B4P_DATA11: R22.1 ; port POD2.IO1
BANK3A_B5N_DATA14: R27.1 ; port POD2.IO8
BANK3A_B5P_CLKUSR: R26.1 ; port POD2.IO2
BANK3A_B7N_PR_DONE: R35.1 ; port POD2.IO10
BANK3A_B7P_PR_ERROR: R34.1 ; port POD2.IO4
BANK3B_B16N: R46.1 ; port POD3.IO3
BANK3B_B16P: R47.1 ; port POD3.IO9
BANK3B_B17N: R50.1 ; port POD3.IO4
BANK3B_B17P: R51.1 ; port POD3.IO10
BANK3B_B21N_BL_CLKOUTN: R43.1 ; port POD3.IO8
BANK3B_B21P_BL_CLKOUTP: R42.1 ; port POD3.IO2
BANK3B_B24N: R39.1 ; port POD3.IO7
BANK3B_B24P: R38.1 ; port POD3.IO1
BANK4A_B33N: R49.1 ; port POD4.IO10
BANK4A_B33P: R48.1 ; port POD4.IO4
BANK4A_B40N: R45.1 ; port POD4.IO9
BANK4A_B40P: R44.1 ; port POD4.IO3
BANK4A_B41N: R41.1 ; port POD4.IO8
BANK4A_B41P: R40.1 ; port POD4.IO2
BANK4A_B48N: R36.1 ; port POD4.IO1
BANK4A_B48P: R37.1 ; port POD4.IO7
POD1_IO1: J9.1(IO1) R20.2 U1.1
POD1_IO2: J9.2(IO2) R24.2 U1.5
POD1_IO3: J9.3(IO3) R28.2 U2.1
POD1_IO4: J9.4(IO4) R32.2 U2.5
POD1_IO7: J9.7(IO7) R21.2 U1.3
POD1_IO8: J9.8(IO8) R25.2 U1.4
POD1_IO9: J9.9(IO9) R29.2 U2.3
POD1_IO10: J9.10(IO10) R33.2 U2.4
POD2_IO1: J10.1(IO1) R22.2 U3.1
POD2_IO2: J10.2(IO2) R26.2 U3.5
POD2_IO3: J10.3(IO3) R30.2 U4.1
POD2_IO4: J10.4(IO4) R34.2 U4.5
POD2_IO7: J10.7(IO7) R23.2 U3.3
POD2_IO8: J10.8(IO8) R27.2 U3.4
POD2_IO9: J10.9(IO9) R31.2 U4.3
POD2_IO10: J10.10(IO10) R35.2 U4.4
POD3_IO1: J12.1(IO1) R38.2 U7.1
POD3_IO2: J12.2(IO2) R42.2 U7.5
POD3_IO3: J12.3(IO3) R46.2 U8.1
POD3_IO4: J12.4(IO4) R50.2 U8.5
POD3_IO7: J12.7(IO7) R39.2 U7.3
POD3_IO8: J12.8(IO8) R43.2 U7.4
POD3_IO9: J12.9(IO9) R47.2 U8.3
POD3_IO10: J12.10(IO10) R51.2 U8.4
POD4_IO1: J11.1(IO1) R36.2 U5.1
POD4_IO2: J11.2(IO2) R40.2 U5.5
POD4_IO3: J11.3(IO3) R44.2 U6.1
POD4_IO4: J11.4(IO4) R48.2 U6.5
POD4_IO7: J11.7(IO7) R37.2 U5.3
POD4_IO8: J11.8(IO8) R41.2 U5.4
POD4_IO9: J11.9(IO9) R45.2 U6.3
POD4_IO10: J11.10(IO10) R49.2 U6.4

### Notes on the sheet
- POD1 Connector
- POD2 Connector
- POD3 Connector
- POD4 Connector
- Title
- Size:
- Date:
- File:
- C
- Number:
- Time:
- Revision:
- Sheet
- of

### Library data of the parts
J9-J12 = 000875: .100 Female Receptacle; Manufacturer: Sullins Electronics Corp.; Manufacturer_PN: PPTC062LJBN-RC; partnumber: 000875; Description 2: 12 Position,  Right Angle
R20-R51 = 000780: Thick-film resistor; Manufacturer: Vishay; partnumber: 000780; Description 2: SM-0402, 1%, 1/16W; Tolerance (%): 1
U1-U8 = 000889: TVS ARRAY - ESD Protection Diode; Manufacturer: ON Semiconductor; partnumber: 000889; Description 2: 4 Diode Array

## Sheet BRKD-ACV-PWR.SCHDOC: FOMD-ACV Breakout Board - Power
size C; Organization: Opal Kelly; Address1: 13500 SW 72nd Ave; Address2: STE 100; Address3: (217)391-3724; Address4: http://www.opalkelly.com; DocumentNumber: 1; Revision: 1.0; SheetNumber: 3; SheetTotal: 3
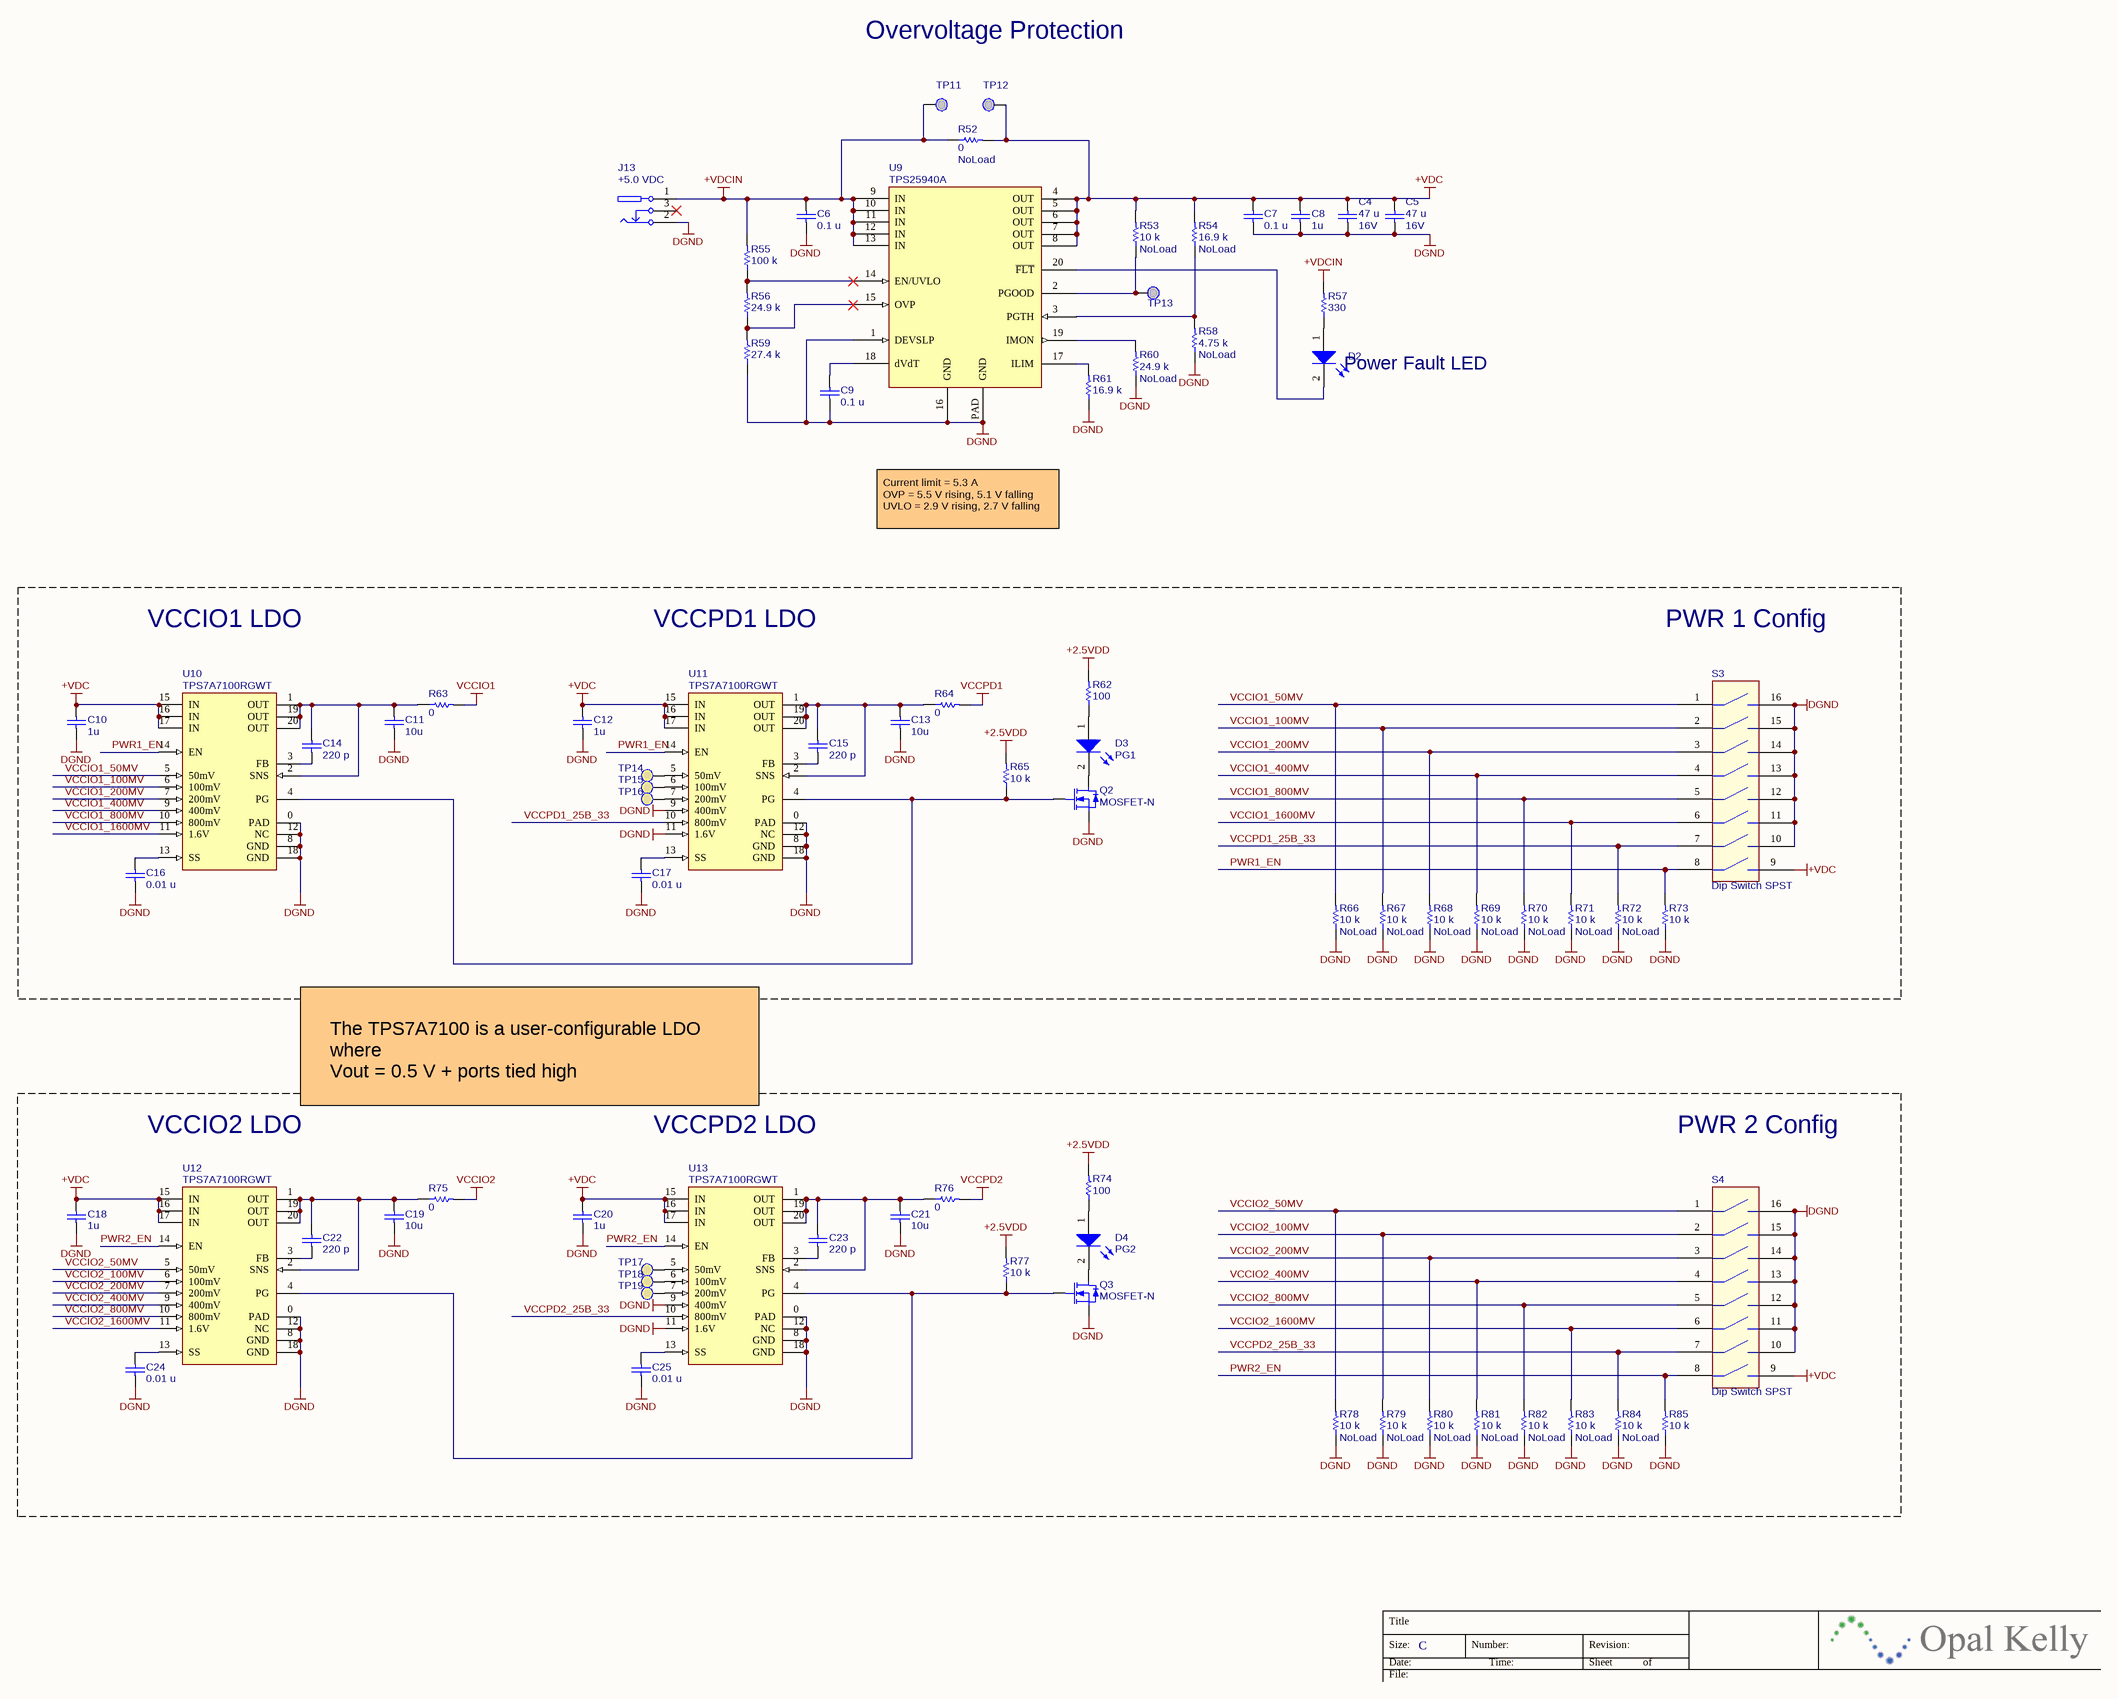
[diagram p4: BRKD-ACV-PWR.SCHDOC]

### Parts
C4  value 47 u  Voltage: 16V  [CAPC3225N]  (hidden comment: GRM32ER61C476KE15K)
C5  value 47 u  Voltage: 16V  [CAPC3225N]  (hidden comment: GRM32ER61C476KE15K)
C6  value 0.1 u  [CAPC1005X06N]  (hidden comment: C0402C104K8PACTU)
C7  value 0.1 u  [CAPC1005X06N]  (hidden comment: C0402C104K8PACTU)
C8  value 1u  [CAPC1005X06N]  (hidden comment: LMK105BJ105KV-F)
C9  value 0.1 u  [CAPC1005X06N]  (hidden comment: C0402C104K8PACTU)
C10  value 1u  [CAPC1005X06N]  (hidden comment: LMK105BJ105KV-F)
C11  value 10u  [CAPC2012N]  (hidden comment: LMK212BJ106KG-T)
C12  value 1u  [CAPC1005X06N]  (hidden comment: LMK105BJ105KV-F)
C13  value 10u  [CAPC2012N]  (hidden comment: LMK212BJ106KG-T)
C14  value 220 p  [CAPC1005X06N]  (hidden comment: C0402C221J5GACTU)
C15  value 220 p  [CAPC1005X06N]  (hidden comment: C0402C221J5GACTU)
C16  value 0.01 u  [CAPC1005X06N]  (hidden comment: C0402C103K4RACTU)
C17  value 0.01 u  [CAPC1005X06N]  (hidden comment: C0402C103K4RACTU)
C18  value 1u  [CAPC1005X06N]  (hidden comment: LMK105BJ105KV-F)
C19  value 10u  [CAPC2012N]  (hidden comment: LMK212BJ106KG-T)
C20  value 1u  [CAPC1005X06N]  (hidden comment: LMK105BJ105KV-F)
C21  value 10u  [CAPC2012N]  (hidden comment: LMK212BJ106KG-T)
C22  value 220 p  [CAPC1005X06N]  (hidden comment: C0402C221J5GACTU)
C23  value 220 p  [CAPC1005X06N]  (hidden comment: C0402C221J5GACTU)
C24  value 0.01 u  [CAPC1005X06N]  (hidden comment: C0402C103K4RACTU)
C25  value 0.01 u  [CAPC1005X06N]  (hidden comment: C0402C103K4RACTU)
D2  FAULT  [CD1608-0603]  (value not drawn)
D3  PG1  [CD1608-0603]
D4  PG2  [CD1608-0603]
J13  +5.0 VDC  [CUI-PJ102A]
Q2  MOSFET-N  [SOT23-95P240X110]
Q3  MOSFET-N  [SOT23-95P240X110]
R52  value 0  [RESC1608N]  (hidden comment: CRCW06030000Z0EA)
R53  value 10 k  [RESC1005X06N]  (hidden comment: CRCW040210K0JNED)
R54  value 16.9 k  [RESC1005X06N]  (hidden comment: CRCW040216K9FKED)
R55  value 100 k  [RESC1005X06N]  (hidden comment: CRCW0402100KFKED)
R56  value 24.9 k  [RESC1005X06N]  (hidden comment: CRCW040224K9FKED)
R57  value 330  [RESC1005X06N]  (hidden comment: CRCW0402330RJNED)
R58  value 4.75 k  [RESC1005X06N]  (hidden comment: CRCW04024K75FKED)
R59  value 27.4 k  [RESC1005X06N]  (hidden comment: CRCW040227K4FKED)
R60  value 24.9 k  [RESC1005X06N]  (hidden comment: CRCW040224K9FKED)
R61  value 16.9 k  [RESC1005X06N]  (hidden comment: CRCW040216K9FKED)
R62  value 100  [RESC1005X06N]  (hidden comment: CRCW0402100RFKED)
R63  value 0  [RESC1608N]  (hidden comment: CRCW06030000Z0EA)
R64  value 0  [RESC1608N]  (hidden comment: CRCW06030000Z0EA)
R65  value 10 k  [RESC1005X06N]  (hidden comment: CRCW040210K0JNED)
R66  value 10 k  [RESC1005X06N]  (hidden comment: CRCW040210K0JNED)
R67  value 10 k  [RESC1005X06N]  (hidden comment: CRCW040210K0JNED)
R68  value 10 k  [RESC1005X06N]  (hidden comment: CRCW040210K0JNED)
R69  value 10 k  [RESC1005X06N]  (hidden comment: CRCW040210K0JNED)
R70  value 10 k  [RESC1005X06N]  (hidden comment: CRCW040210K0JNED)
R71  value 10 k  [RESC1005X06N]  (hidden comment: CRCW040210K0JNED)
R72  value 10 k  [RESC1005X06N]  (hidden comment: CRCW040210K0JNED)
R73  value 10 k  [RESC1005X06N]  (hidden comment: CRCW040210K0JNED)
R74  value 100  [RESC1005X06N]  (hidden comment: CRCW0402100RFKED)
R75  value 0  [RESC1608N]  (hidden comment: CRCW06030000Z0EA)
R76  value 0  [RESC1608N]  (hidden comment: CRCW06030000Z0EA)
R77  value 10 k  [RESC1005X06N]  (hidden comment: CRCW040210K0JNED)
R78  value 10 k  [RESC1005X06N]  (hidden comment: CRCW040210K0JNED)
R79  value 10 k  [RESC1005X06N]  (hidden comment: CRCW040210K0JNED)
R80  value 10 k  [RESC1005X06N]  (hidden comment: CRCW040210K0JNED)
R81  value 10 k  [RESC1005X06N]  (hidden comment: CRCW040210K0JNED)
R82  value 10 k  [RESC1005X06N]  (hidden comment: CRCW040210K0JNED)
R83  value 10 k  [RESC1005X06N]  (hidden comment: CRCW040210K0JNED)
R84  value 10 k  [RESC1005X06N]  (hidden comment: CRCW040210K0JNED)
R85  value 10 k  [RESC1005X06N]  (hidden comment: CRCW040210K0JNED)
S3  Dip Switch SPST  [219-8xxST]
S4  Dip Switch SPST  [219-8xxST]
TP11  TP-PTH-25/45  [TP-PTH-25/45]  (value not drawn)
TP12  TP-PTH-25/45  [TP-PTH-25/45]  (value not drawn)
TP13  TP-PTH-25/45  [TP-PTH-25/45]  (value not drawn)
TP14  TESTPOINT-SMD20  [TP-SMD20]  (value not drawn)
TP15  TESTPOINT-SMD20  [TP-SMD20]  (value not drawn)
TP16  TESTPOINT-SMD20  [TP-SMD20]  (value not drawn)
TP17  TESTPOINT-SMD20  [TP-SMD20]  (value not drawn)
TP18  TESTPOINT-SMD20  [TP-SMD20]  (value not drawn)
TP19  TESTPOINT-SMD20  [TP-SMD20]  (value not drawn)
U9  TPS25940A  [TPS25940]
U10  TPS7A7100RGWT  [S-PVQN-N20]
U11  TPS7A7100RGWT  [S-PVQN-N20]
U12  TPS7A7100RGWT  [S-PVQN-N20]
U13  TPS7A7100RGWT  [S-PVQN-N20]

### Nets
+2.5VDD: R62.2 R65.2 R74.2 R77.2
+VDC: C4.1 C5.1 C7.2 C8.2 C10.2 C12.2 C18.2 C20.2 R52.2 R53.2 R54.2 S3.9 S4.9 TP12.1(PIN) U9.4(OUT) U9.5(OUT) U9.6(OUT) U9.7(OUT) U9.8(OUT) U10.15(IN) U10.16(IN) U10.17(IN) U11.15(IN) U11.16(IN) U11.17(IN) U12.15(IN) U12.16(IN) U12.17(IN) U13.15(IN) U13.16(IN) U13.17(IN)
+VDCIN: C6.2 J13.1 R52.1 R55.2 R57.2 TP11.1(PIN) U9.9(IN) U9.10(IN) U9.11(IN) U9.12(IN) U9.13(IN)
DGND: C4.2 C5.2 C6.1 C7.1 C8.1 C9.1 C10.1 C11.1 C12.1 C13.1 C16.1 C17.1 C18.1 C19.1 C20.1 C21.1 C24.1 C25.1 J13.2 Q2.2(S) Q3.2(S) R58.1 R59.1 R60.1 R61.1 R66.1 R67.1 R68.1 R69.1 R70.1 R71.1 R72.1 R73.1 R78.1 R79.1 R80.1 R81.1 R82.1 R83.1 R84.1 R85.1 S3.10 S3.11 S3.12 S3.13 S3.14 S3.15 S3.16 S4.10 S4.11 S4.12 S4.13 S4.14 S4.15 S4.16 U9.1(DEVSLP) U9.16(GND) U9.PAD(GND) U10.0(PAD) U10.8(GND) U10.12(NC) U10.18(GND) U11.0(PAD) U11.8(GND) U11.9(400mV) U11.11(1.6V) U11.12(NC) U11.18(GND) U12.0(PAD) U12.8(GND) U12.12(NC) U12.18(GND) U13.0(PAD) U13.8(GND) U13.9(400mV) U13.11(1.6V) U13.12(NC) U13.18(GND)
VCCIO1: R63.2
VCCIO2: R75.2
VCCPD1: R64.2
VCCPD2: R76.2
PWR1_EN: R73.2 S3.8 U10.14(EN) U11.14(EN)
PWR2_EN: R85.2 S4.8 U12.14(EN) U13.14(EN)
VCCIO1_50MV: R66.2 S3.1 U10.5(50mV)
VCCIO1_100MV: R67.2 S3.2 U10.6(100mV)
VCCIO1_200MV: R68.2 S3.3 U10.7(200mV)
VCCIO1_400MV: R69.2 S3.4 U10.9(400mV)
VCCIO1_800MV: R70.2 S3.5 U10.10(800mV)
VCCIO1_1600MV: R71.2 S3.6 U10.11(1.6V)
VCCIO2_50MV: R78.2 S4.1 U12.5(50mV)
VCCIO2_100MV: R79.2 S4.2 U12.6(100mV)
VCCIO2_200MV: R80.2 S4.3 U12.7(200mV)
VCCIO2_400MV: R81.2 S4.4 U12.9(400mV)
VCCIO2_800MV: R82.2 S4.5 U12.10(800mV)
VCCIO2_1600MV: R83.2 S4.6 U12.11(1.6V)
VCCPD1_25B_33: R72.2 S3.7 U11.10(800mV)
VCCPD2_25B_33: R84.2 S4.7 U13.10(800mV)
NetC9_2: C9.2 U9.18(dVdT)
NetC11_2: C11.2 C14.2 R63.1 U10.1(OUT) U10.2(SNS) U10.19(OUT) U10.20(OUT)
NetC13_2: C13.2 C15.2 R64.1 U11.1(OUT) U11.2(SNS) U11.19(OUT) U11.20(OUT)
NetC14_1: C14.1 U10.3(FB)
NetC15_1: C15.1 U11.3(FB)
NetC16_2: C16.2 U10.13(SS)
NetC17_2: C17.2 U11.13(SS)
NetC19_2: C19.2 C22.2 R75.1 U12.1(OUT) U12.2(SNS) U12.19(OUT) U12.20(OUT)
NetC21_2: C21.2 C23.2 R76.1 U13.1(OUT) U13.2(SNS) U13.19(OUT) U13.20(OUT)
NetC22_1: C22.1 U12.3(FB)
NetC23_1: C23.1 U13.3(FB)
NetC24_2: C24.2 U12.13(SS)
NetC25_2: C25.2 U13.13(SS)
NetD2_1: D2.1(A) R57.1
NetD2_2: D2.2(K) U9.20(~{FLT})
NetD3_1: D3.1(A) R62.1
NetD3_2: D3.2(K) Q2.3(D)
NetD4_1: D4.1(A) R74.1
NetD4_2: D4.2(K) Q3.3(D)
NetQ2_1: Q2.1(G) R65.1 U10.4(PG) U11.4(PG)
NetQ3_1: Q3.1(G) R77.1 U12.4(PG) U13.4(PG)
NetR53_1: R53.1 TP13.1(PIN) U9.2(PGOOD)
NetR54_1: R54.1 R58.2 U9.3(PGTH)
NetR55_1: R55.1 R56.2 U9.14(EN/UVLO)
NetR56_1: R56.1 R59.2 U9.15(OVP)
NetR60_2: R60.2 U9.19(IMON)
NetR61_2: R61.2 U9.17(ILIM)
NetTP14_1: TP14.1(PIN) U11.5(50mV)
NetTP15_1: TP15.1(PIN) U11.6(100mV)
NetTP16_1: TP16.1(PIN) U11.7(200mV)
NetTP17_1: TP17.1(PIN) U13.5(50mV)
NetTP18_1: TP18.1(PIN) U13.6(100mV)
NetTP19_1: TP19.1(PIN) U13.7(200mV)

Not connected (* = marked no-connect by the designer): J13 3*

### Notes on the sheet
- Overvoltage Protection
- (near D2) Power Fault LED
- Current limit = 5.3 A
  OVP = 5.5 V rising, 5.1 V falling
  UVLO = 2.9 V rising, 2.7 V falling
- VCCIO1 LDO
- VCCPD1 LDO
- PWR 1 Config
- VCCIO2 LDO
- The TPS7A7100 is a user-configurable LDO where
  Vout = 0.5 V + ports tied high
- VCCPD2 LDO
- PWR 2 Config
- Title
- Size:
- Date:
- File:
- C
- Number:
- Time:
- Revision:
- Sheet
- of

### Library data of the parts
C4 C5 = 001368: Ceramic Capacitor; Manufacturer: Murata; partnumber: 001368; Description 2: 1210, 16V, 10%; ValueFloat: 4.7E-5; Tolerance (%): 10; x_voltage-rating: 16; x_lifecycle_status: Production
C6 C7 C9 = 000070: as C1 on sheet BRKD-ACV-IO-HDR
C8 C10 C12 C18 C20 = 000480: Ceramic capacitor; Manufacturer: Taiyo Yuden; partnumber: 000480; Description 2: SM-0402, 10%, 10v; ValueFloat: 1E-6; Tolerance (%): 10
C11 C13 C19 C21 = 000491: Ceramic capacitor; Manufacturer: Taiyo Yuden; partnumber: 000491; Description 2: SM-0805, 10%, 10v; ValueFloat: 1E-5; Tolerance (%): 10
C14 C15 C22 C23 = 001219: Ceramic capacitor; Manufacturer: Kemet; partnumber: 001219; Description 2: SM-0402, 5%, 50v; ValueFloat: 2.2E-10; Tolerance (%): 5
C16 C17 C24 C25 = 000295: Ceramic Capacitor; Manufacturer: Kemet; partnumber: 000295; Description 2: SM-0402, 10%, 6.3V, X5R; ValueFloat: 1E-8; Tolerance (%): 10
D2 = 000011: LED; Manufacturer: Lite-On; Manufacturer_PN: LTST-C190EKT; partnumber: 000011; Description 2: SM-0603, red-orange
D3 D4 = 000012: as D1 on sheet BRKD-ACV-IO-HDR
J13 = 000356: DC power connector - high current; Manufacturer: CUI Inc.; Manufacturer_PN: PJ-102AH; partnumber: 000356; Description 2: 2.1mm / 5.5mm
Q2 Q3 = 001237: as Q1 on sheet BRKD-ACV-IO-HDR
R52 R63 R64 R75 R76 = 000411: as R13 on sheet BRKD-ACV-IO-HDR
R53 R65-R73 R77-R85 = 000759: as R2 on sheet BRKD-ACV-IO-HDR
R54 = 001332: Thick-film resistor; Manufacturer: Vishay; partnumber: 001332; Description 2: SM-0402, 1%, 1/16W; ValueFloat: 16900; Tolerance (%): 1; x_lifecycle_status: Production
R55 = 001070: Thick-film resistor; Manufacturer: Vishay; partnumber: 001070; Description 2: SM-0402, 1%, 1/16W; ValueFloat: 100000; Tolerance (%): 1
R56 R60 = 000934: Thick-film resistor; Manufacturer: Vishay; partnumber: 000934; Description 2: SM-0402, 1%, 1/16W; ValueFloat: 24900; Tolerance (%): 1
R57 = 000803: Thick-film resistor; Manufacturer: Vishay; partnumber: 000803; Description 2: SM-0402, 5%, 1/16W; Tolerance (%): 5
R58 = 001008: Thick-film resistor; Manufacturer: Vishay; partnumber: 001008; Description 2: SM-0402, 1%, 1/16W; ValueFloat: 4750; Tolerance (%): 1
R59 = 001032: Thick-film resistor; Manufacturer: Vishay; partnumber: 001032; Description 2: SM-0402, 1%, 1/16W; ValueFloat: 27400; Tolerance (%): 1
R61 = 001332: Thick-film resistor; Manufacturer: Vishay; partnumber: 001332; Description 2: SM-0402, 1%, 1/16W; ValueFloat: 16900; Tolerance (%): 1
R62 R74 = 000827: as R15 on sheet BRKD-ACV-IO-HDR
S3 S4 = 000310: Sealed, 8 SPST DIP switch; PartNumber: 000310; Manufacturer: CTS; Manufacturer_PN: 219-8MST; Description 2: Extended Actuator
TP11-TP13 = TP-PTH-25/45: Test point, plated through-hole, 25/45mil
TP14-TP19 = TESTPOINT-SMD20: Test point, surface-mount, 20mil
U9 = 001325: 18V eFuse with reverse- /over-voltage protection and current limiting, auto-retry; Manufacturer: Texas Instruments; partnumber: 001325; Description 2: 2.7V-18V, 5.3A current limit, 42 mOhm R_ON, 3x4mm WQFN-20; x_lifecycle_status: Production
U10-U13 = 001209: LDO voltage regulator; Manufacturer: Texas Instruments; partnumber: 001209; Description 2: Vin: 1.5V-6.5V Vout Fixed: 0.9V-3.5V Vout Adj:0,9V-5V

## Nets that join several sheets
+2.5VDD: BRKD-ACV-IO-HDR (6 pins), BRKD-ACV-PWR (R62.2 R65.2 R74.2 R77.2)
+VDC: BRKD-ACV-IO-HDR (6 pins), BRKD-ACV-PWR (31 pins)
DGND: BRKD-ACV-IO-HDR (57 pins), BRKD-ACV-IO-PMOD (16 pins), BRKD-ACV-PWR (78 pins)
VCCIO1: BRKD-ACV-IO-HDR (6 pins), BRKD-ACV-IO-PMOD (J9.6 J9.12 J10.6 J10.12), BRKD-ACV-PWR (R63.2)
VCCIO2: BRKD-ACV-IO-HDR (5 pins), BRKD-ACV-IO-PMOD (J11.6 J11.12 J12.6 J12.12), BRKD-ACV-PWR (R75.2)
VCCPD1: BRKD-ACV-IO-HDR (6 pins), BRKD-ACV-PWR (R64.2)
VCCPD2: BRKD-ACV-IO-HDR (J1.189 J6.35 J7.37 TP9.1), BRKD-ACV-PWR (R76.2)
BANK2A_L13N: BRKD-ACV-IO-HDR (J1.11 J2.4), BRKD-ACV-IO-PMOD (R33.1)
BANK2A_L13P: BRKD-ACV-IO-HDR (J1.13 J2.3), BRKD-ACV-IO-PMOD (R32.1)
BANK2A_L14N: BRKD-ACV-IO-HDR (J1.15 J2.6), BRKD-ACV-IO-PMOD (R29.1)
BANK2A_L14P: BRKD-ACV-IO-HDR (J1.17 J2.5), BRKD-ACV-IO-PMOD (R28.1)
BANK2A_L15N: BRKD-ACV-IO-HDR (J1.19 J2.8), BRKD-ACV-IO-PMOD (R25.1)
BANK2A_L15P: BRKD-ACV-IO-HDR (J1.21 J2.7), BRKD-ACV-IO-PMOD (R24.1)
BANK2A_L16N: BRKD-ACV-IO-HDR (J1.25 J2.9), BRKD-ACV-IO-PMOD (R20.1)
BANK2A_L16P: BRKD-ACV-IO-HDR (J1.23 J2.10), BRKD-ACV-IO-PMOD (R21.1)
BANK3A_B1N_DATA6: BRKD-ACV-IO-HDR (J1.57 J4.7), BRKD-ACV-IO-PMOD (R30.1)
BANK3A_B1P_DATA8: BRKD-ACV-IO-HDR (J1.55 J4.8), BRKD-ACV-IO-PMOD (R31.1)
BANK3A_B4N_DATA9: BRKD-ACV-IO-HDR (J1.65 J4.12), BRKD-ACV-IO-PMOD (R23.1)
BANK3A_B4P_DATA11: BRKD-ACV-IO-HDR (J1.67 J4.11), BRKD-ACV-IO-PMOD (R22.1)
BANK3A_B5N_DATA14: BRKD-ACV-IO-HDR (J1.59 J4.10), BRKD-ACV-IO-PMOD (R27.1)
BANK3A_B5P_CLKUSR: BRKD-ACV-IO-HDR (J1.61 J4.9), BRKD-ACV-IO-PMOD (R26.1)
BANK3A_B7N_PR_DONE: BRKD-ACV-IO-HDR (J1.51 J4.6), BRKD-ACV-IO-PMOD (R35.1)
BANK3A_B7P_PR_ERROR: BRKD-ACV-IO-HDR (J1.53 J4.5), BRKD-ACV-IO-PMOD (R34.1)
BANK3B_B16N: BRKD-ACV-IO-HDR (J1.95 J4.25), BRKD-ACV-IO-PMOD (R46.1)
BANK3B_B16P: BRKD-ACV-IO-HDR (J1.93 J4.26), BRKD-ACV-IO-PMOD (R47.1)
BANK3B_B17N: BRKD-ACV-IO-HDR (J1.89 J4.21), BRKD-ACV-IO-PMOD (R50.1)
BANK3B_B17P: BRKD-ACV-IO-HDR (J1.87 J4.22), BRKD-ACV-IO-PMOD (R51.1)
BANK3B_B21N_BL_CLKOUTN: BRKD-ACV-IO-HDR (J1.97 J4.28), BRKD-ACV-IO-PMOD (R43.1)
BANK3B_B21P_BL_CLKOUTP: BRKD-ACV-IO-HDR (J1.99 J4.27), BRKD-ACV-IO-PMOD (R42.1)
BANK3B_B24N: BRKD-ACV-IO-HDR (J1.101 J4.30), BRKD-ACV-IO-PMOD (R39.1)
BANK3B_B24P: BRKD-ACV-IO-HDR (J1.103 J4.29), BRKD-ACV-IO-PMOD (R38.1)
BANK4A_B33N: BRKD-ACV-IO-HDR (J1.143 J6.12), BRKD-ACV-IO-PMOD (R49.1)
BANK4A_B33P: BRKD-ACV-IO-HDR (J1.145 J6.11), BRKD-ACV-IO-PMOD (R48.1)
BANK4A_B40N: BRKD-ACV-IO-HDR (J1.149 J6.14), BRKD-ACV-IO-PMOD (R45.1)
BANK4A_B40P: BRKD-ACV-IO-HDR (J1.151 J6.13), BRKD-ACV-IO-PMOD (R44.1)
BANK4A_B41N: BRKD-ACV-IO-HDR (J1.153 J6.16), BRKD-ACV-IO-PMOD (R41.1)
BANK4A_B41P: BRKD-ACV-IO-HDR (J1.155 J6.15), BRKD-ACV-IO-PMOD (R40.1)
BANK4A_B48N: BRKD-ACV-IO-HDR (J1.159 J6.17), BRKD-ACV-IO-PMOD (R36.1)
BANK4A_B48P: BRKD-ACV-IO-HDR (J1.157 J6.18), BRKD-ACV-IO-PMOD (R37.1)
